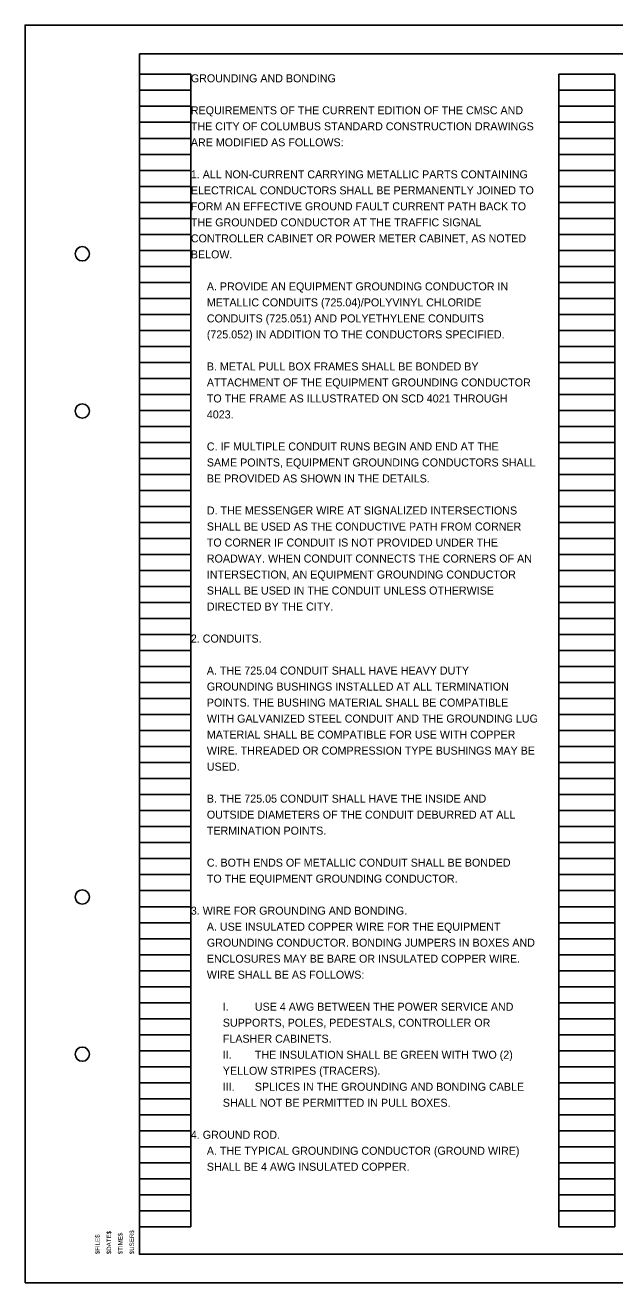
# Model space of a CAD drawing. Extents: x -25.6 to 66.7, y -23.1 to 37.2.
# Drawn here: x -0.51 to 9.81, y -7.51 to 14.49 of the extents above; entities that cross this region are included whole.
import ezdxf

# ---------------------------------------------------------------- set-up
doc = ezdxf.new("R2010")
doc.units = 0
for name, color, linetype in [('PF_P_Text', 7, 'Continuous'), ('SC_Scratch1', 7, 'Continuous'), ('SH_Cut_Line', 7, 'Continuous'), ('SH_Text', 7, 'Continuous'), ('TX_P_Misc', 7, 'Continuous')]:
    doc.layers.add(name, color=color, linetype=linetype)

msp = doc.modelspace()

# ---------------------------------------------------------------- linework, layer by layer
at = {"layer": 'PF_P_Text'}
msp.add_lwpolyline([(1.494, 13.992), (32.994, 13.992), (32.994, -7.008), (1.494, -7.008)], close=True, dxfattribs=at)
for centre in [(0.494, 10.492), (0.494, 7.742), (0.494, -0.758), (0.494, -3.508)]:
    msp.add_circle(centre, 0.125, dxfattribs=at)
at = {"layer": 'SC_Scratch1'}
for p, q in [((1.494, -6.528), (1.494, 13.632)), ((1.494, 13.632), (2.394, 13.632)), ((2.394, -6.528), (2.394, 13.632)), ((8.834, -6.528), (8.834, 13.632)), ((8.834, 13.632), (9.814, 13.632)), ((9.814, -6.528), (9.814, 13.632)), ((1.494, 13.352), (2.394, 13.352)), ((8.834, 13.352), (9.814, 13.352)), ((1.494, 13.072), (2.394, 13.072)), ((8.834, 13.072), (9.814, 13.072)), ((1.494, 12.792), (2.394, 12.792)), ((8.834, 12.792), (9.814, 12.792)), ((1.494, 12.512), (2.394, 12.512)), ((8.834, 12.512), (9.814, 12.512)), ((1.494, 12.232), (2.394, 12.232)), ((8.834, 12.232), (9.814, 12.232)), ((1.494, 11.952), (2.394, 11.952)), ((8.834, 11.952), (9.814, 11.952)), ((1.494, 11.672), (2.394, 11.672)), ((8.834, 11.672), (9.814, 11.672)), ((1.494, 11.392), (2.394, 11.392)), ((8.834, 11.392), (9.814, 11.392)), ((1.494, 11.112), (2.394, 11.112)), ((8.834, 11.112), (9.814, 11.112)), ((1.494, 10.832), (2.394, 10.832)), ((8.834, 10.832), (9.814, 10.832)), ((1.494, 10.552), (2.394, 10.552)), ((8.834, 10.552), (9.814, 10.552)), ((1.494, 10.272), (2.394, 10.272)), ((8.834, 10.272), (9.814, 10.272)), ((1.494, 9.992), (2.394, 9.992)), ((8.834, 9.992), (9.814, 9.992)), ((1.494, 9.712), (2.394, 9.712)), ((8.834, 9.712), (9.814, 9.712)), ((1.494, 9.432), (2.394, 9.432)), ((8.834, 9.432), (9.814, 9.432)), ((1.494, 9.152), (2.394, 9.152)), ((8.834, 9.152), (9.814, 9.152)), ((1.494, 8.872), (2.394, 8.872)), ((8.834, 8.872), (9.814, 8.872)), ((1.494, 8.592), (2.394, 8.592)), ((8.834, 8.592), (9.814, 8.592)), ((1.494, 8.312), (2.394, 8.312)), ((8.834, 8.312), (9.814, 8.312)), ((1.494, 8.032), (2.394, 8.032)), ((8.834, 8.032), (9.814, 8.032)), ((1.494, 7.752), (2.394, 7.752)), ((8.834, 7.752), (9.814, 7.752)), ((1.494, 7.472), (2.394, 7.472)), ((8.834, 7.472), (9.814, 7.472)), ((1.494, 7.192), (2.394, 7.192)), ((8.834, 7.192), (9.814, 7.192)), ((1.494, 6.912), (2.394, 6.912)), ((8.834, 6.912), (9.814, 6.912)), ((1.494, 6.632), (2.394, 6.632)), ((8.834, 6.632), (9.814, 6.632)), ((1.494, 6.352), (2.394, 6.352)), ((8.834, 6.352), (9.814, 6.352)), ((1.494, 6.072), (2.394, 6.072)), ((8.834, 6.072), (9.814, 6.072)), ((1.494, 5.792), (2.394, 5.792)), ((8.834, 5.792), (9.814, 5.792)), ((1.494, 5.512), (2.394, 5.512)), ((8.834, 5.512), (9.814, 5.512)), ((1.494, 5.232), (2.394, 5.232)), ((8.834, 5.232), (9.814, 5.232)), ((1.494, 4.952), (2.394, 4.952)), ((8.834, 4.952), (9.814, 4.952)), ((1.494, 4.672), (2.394, 4.672)), ((8.834, 4.672), (9.814, 4.672)), ((1.494, 4.392), (2.394, 4.392)), ((8.834, 4.392), (9.814, 4.392)), ((1.494, 4.112), (2.394, 4.112)), ((8.834, 4.112), (9.814, 4.112)), ((1.494, 3.832), (2.394, 3.832)), ((8.834, 3.832), (9.814, 3.832)), ((1.494, 3.552), (2.394, 3.552)), ((8.834, 3.552), (9.814, 3.552)), ((1.494, 3.272), (2.394, 3.272)), ((8.834, 3.272), (9.814, 3.272)), ((1.494, 2.992), (2.394, 2.992)), ((8.834, 2.992), (9.814, 2.992)), ((1.494, 2.712), (2.394, 2.712)), ((8.834, 2.712), (9.814, 2.712)), ((1.494, 2.432), (2.394, 2.432)), ((8.834, 2.432), (9.814, 2.432)), ((1.494, 2.152), (2.394, 2.152)), ((8.834, 2.152), (9.814, 2.152)), ((1.494, 1.872), (2.394, 1.872)), ((8.834, 1.872), (9.814, 1.872)), ((1.494, 1.592), (2.394, 1.592)), ((8.834, 1.592), (9.814, 1.592)), ((1.494, 1.312), (2.394, 1.312)), ((8.834, 1.312), (9.814, 1.312)), ((1.494, 1.032), (2.394, 1.032)), ((8.834, 1.032), (9.814, 1.032)), ((1.494, 0.752), (2.394, 0.752)), ((8.834, 0.752), (9.814, 0.752)), ((1.494, 0.472), (2.394, 0.472)), ((8.834, 0.472), (9.814, 0.472)), ((1.494, 0.192), (2.394, 0.192)), ((8.834, 0.192), (9.814, 0.192)), ((1.494, -0.088), (2.394, -0.088)), ((8.834, -0.088), (9.814, -0.088)), ((1.494, -0.368), (2.394, -0.368)), ((8.834, -0.368), (9.814, -0.368)), ((1.494, -0.648), (2.394, -0.648)), ((8.834, -0.648), (9.814, -0.648)), ((1.494, -0.928), (2.394, -0.928)), ((8.834, -0.928), (9.814, -0.928)), ((1.494, -1.208), (2.394, -1.208)), ((8.834, -1.208), (9.814, -1.208)), ((1.494, -1.488), (2.394, -1.488)), ((8.834, -1.488), (9.814, -1.488)), ((1.494, -1.768), (2.394, -1.768)), ((8.834, -1.768), (9.814, -1.768)), ((1.494, -2.048), (2.394, -2.048)), ((8.834, -2.048), (9.814, -2.048)), ((1.494, -2.328), (2.394, -2.328)), ((8.834, -2.328), (9.814, -2.328)), ((1.494, -2.608), (2.394, -2.608)), ((8.834, -2.608), (9.814, -2.608)), ((1.494, -2.888), (2.394, -2.888)), ((8.834, -2.888), (9.814, -2.888)), ((1.494, -3.168), (2.394, -3.168)), ((8.834, -3.168), (9.814, -3.168)), ((1.494, -3.448), (2.394, -3.448)), ((8.834, -3.448), (9.814, -3.448)), ((1.494, -3.728), (2.394, -3.728)), ((8.834, -3.728), (9.814, -3.728)), ((1.494, -4.008), (2.394, -4.008)), ((8.834, -4.008), (9.814, -4.008)), ((1.494, -4.288), (2.394, -4.288)), ((8.834, -4.288), (9.814, -4.288)), ((1.494, -4.568), (2.394, -4.568)), ((8.834, -4.568), (9.814, -4.568)), ((1.494, -4.848), (2.394, -4.848)), ((8.834, -4.848), (9.814, -4.848)), ((1.494, -5.128), (2.394, -5.128)), ((8.834, -5.128), (9.814, -5.128)), ((1.494, -5.408), (2.394, -5.408)), ((8.834, -5.408), (9.814, -5.408)), ((1.494, -5.688), (2.394, -5.688)), ((8.834, -5.688), (9.814, -5.688)), ((1.494, -5.968), (2.394, -5.968)), ((8.834, -5.968), (9.814, -5.968)), ((1.494, -6.248), (2.394, -6.248)), ((8.834, -6.248), (9.814, -6.248)), ((1.494, -6.528), (2.394, -6.528)), ((8.834, -6.528), (9.814, -6.528)), ((-0.506, -7.508), (-0.506, -7.508))]:
    msp.add_line(p, q, dxfattribs=at)
at = {"layer": 'SH_Cut_Line'}
msp.add_lwpolyline([(-0.506, -7.508), (33.494, -7.508), (33.494, 14.492), (-0.506, 14.492)], close=True, dxfattribs=at)

# ---------------------------------------------------------------- texts
at = {"layer": 'SH_Text'}
for s, p in [('GROUNDING AND BONDING', (2.394, 13.492)), ('REQUIREMENTS OF THE CURRENT EDITION OF THE CMSC AND ', (2.394, 12.932)), ('THE CITY OF COLUMBUS STANDARD CONSTRUCTION DRAWINGS ', (2.394, 12.652)), ('ARE MODIFIED AS FOLLOWS:', (2.394, 12.372)), ('1. ALL NON-CURRENT CARRYING METALLIC PARTS CONTAINING ', (2.394, 11.812)), ('ELECTRICAL CONDUCTORS SHALL BE PERMANENTLY JOINED TO ', (2.394, 11.532)), ('FORM AN EFFECTIVE GROUND FAULT CURRENT PATH BACK TO ', (2.394, 11.252)), ('THE GROUNDED CONDUCTOR AT THE TRAFFIC SIGNAL ', (2.394, 10.972)), ('CONTROLLER CABINET OR POWER METER CABINET, AS NOTED ', (2.394, 10.692)), ('BELOW.', (2.394, 10.412)), ('A. PROVIDE AN EQUIPMENT GROUNDING CONDUCTOR IN ', (2.674, 9.852)), ('METALLIC CONDUITS (725.04)/POLYVINYL CHLORIDE ', (2.674, 9.572)), ('CONDUITS (725.051) AND POLYETHYLENE CONDUITS ', (2.674, 9.292)), ('(725.052) IN ADDITION TO THE CONDUCTORS SPECIFIED.', (2.674, 9.012)), ('B. METAL PULL BOX FRAMES SHALL BE BONDED BY ', (2.674, 8.452)), ('ATTACHMENT OF THE EQUIPMENT GROUNDING CONDUCTOR ', (2.674, 8.172)), ('TO THE FRAME AS ILLUSTRATED ON SCD 4021 THROUGH ', (2.674, 7.892)), ('4023.', (2.674, 7.612)), ('C. IF MULTIPLE CONDUIT RUNS BEGIN AND END AT THE ', (2.674, 7.052)), ('SAME POINTS, EQUIPMENT GROUNDING CONDUCTORS SHALL ', (2.674, 6.772)), ('BE PROVIDED AS SHOWN IN THE DETAILS.', (2.674, 6.492)), ('D. THE MESSENGER WIRE AT SIGNALIZED INTERSECTIONS ', (2.674, 5.932)), ('SHALL BE USED AS THE CONDUCTIVE PATH FROM CORNER ', (2.674, 5.652)), ('TO CORNER IF CONDUIT IS NOT PROVIDED UNDER THE ', (2.674, 5.372)), ('ROADWAY. WHEN CONDUIT CONNECTS THE CORNERS OF AN ', (2.674, 5.092)), ('INTERSECTION, AN EQUIPMENT GROUNDING CONDUCTOR ', (2.674, 4.812)), ('SHALL BE USED IN THE CONDUIT UNLESS OTHERWISE ', (2.674, 4.532)), ('DIRECTED BY THE CITY.', (2.674, 4.252)), ('2. CONDUITS.', (2.394, 3.692)), ('A. THE 725.04 CONDUIT SHALL HAVE HEAVY DUTY ', (2.674, 3.132)), ('GROUNDING BUSHINGS INSTALLED AT ALL TERMINATION ', (2.674, 2.852)), ('POINTS. THE BUSHING MATERIAL SHALL BE COMPATIBLE ', (2.674, 2.572)), ('WITH GALVANIZED STEEL CONDUIT AND THE GROUNDING LUG ', (2.674, 2.292)), ('MATERIAL SHALL BE COMPATIBLE FOR USE WITH COPPER ', (2.674, 2.012)), ('WIRE. THREADED OR COMPRESSION TYPE BUSHINGS MAY BE ', (2.674, 1.732)), ('USED.', (2.674, 1.452)), ('B. THE 725.05 CONDUIT SHALL HAVE THE INSIDE AND ', (2.674, 0.892)), ('OUTSIDE DIAMETERS OF THE CONDUIT DEBURRED AT ALL ', (2.674, 0.612)), ('TERMINATION POINTS.', (2.674, 0.332)), ('C. BOTH ENDS OF METALLIC CONDUIT SHALL BE BONDED ', (2.674, -0.228)), ('TO THE EQUIPMENT GROUNDING CONDUCTOR.', (2.674, -0.508)), ('3. WIRE FOR GROUNDING AND BONDING.', (2.394, -1.068)), ('A. USE INSULATED COPPER WIRE FOR THE EQUIPMENT ', (2.674, -1.348)), ('GROUNDING CONDUCTOR. BONDING JUMPERS IN BOXES AND ', (2.674, -1.628)), ('ENCLOSURES MAY BE BARE OR INSULATED COPPER WIRE. ', (2.674, -1.908)), ('WIRE SHALL BE AS FOLLOWS:', (2.674, -2.188)), ('I.', (2.954, -2.748)), ('USE 4 AWG BETWEEN THE POWER SERVICE AND ', (3.514, -2.748)), ('SUPPORTS, POLES, PEDESTALS, CONTROLLER OR ', (2.954, -3.028)), ('FLASHER CABINETS.', (2.954, -3.308)), ('II.', (2.954, -3.588)), ('THE INSULATION SHALL BE GREEN WITH TWO (2) ', (3.514, -3.588)), ('YELLOW STRIPES (TRACERS). ', (2.954, -3.868)), ('III.', (2.954, -4.148)), ('SPLICES IN THE GROUNDING AND BONDING CABLE ', (3.514, -4.148)), ('SHALL NOT BE PERMITTED IN PULL BOXES.', (2.954, -4.428)), ('4. GROUND ROD.', (2.394, -4.988)), ('A. THE TYPICAL GROUNDING CONDUCTOR (GROUND WIRE) ', (2.674, -5.268)), ('SHALL BE 4 AWG INSULATED COPPER.', (2.674, -5.548))]:
    msp.add_text(s, height=0.14, dxfattribs=at).set_placement(p)
at = {"layer": 'TX_P_Misc'}
for s, p in [('$FILE$', (0.799, -7.008)), ('$DATE$', (0.999, -7.008)), ('$TIME$', (1.199, -7.008)), ('$USER$', (1.399, -7.008))]:
    msp.add_text(s, height=0.078, rotation=90, dxfattribs=at).set_placement(p)

doc.saveas('drawing.dxf')
